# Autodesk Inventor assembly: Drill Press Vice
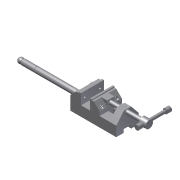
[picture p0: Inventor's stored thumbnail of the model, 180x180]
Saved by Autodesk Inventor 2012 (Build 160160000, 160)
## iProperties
Created: 2009-05
Part Number: Drill Press Vice
Document SubType Name: Assembly
Designer: Sham
Author: Sham
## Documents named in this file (9)
- C:\Users\CadCim\Documents\SAILESH\inventor-2011-fact-prt\c13-inv-2011-prt\c13_inv_2012_prt\Tutorials\c13_tut02_inv\Drill Press Vice.iam
- C:\Users\CadCim\Documents\SAILESH\inventor-2011-fact-prt\c13-inv-2011-prt\c13_inv_2012_prt\Tutorials\c13_tut02_inv\Base.ipt
- C:\Users\CadCim\Documents\SAILESH\inventor-2011-fact-prt\c13-inv-2011-prt\c13_inv_2012_prt\Tutorials\c13_tut02_inv\Safety Handle.ipt
- C:\Users\CadCim\Documents\SAILESH\inventor-2011-fact-prt\c13-inv-2011-prt\c13_inv_2012_prt\Tutorials\c13_tut02_inv\Jaw Face.ipt
- C:\Users\CadCim\Documents\SAILESH\inventor-2011-fact-prt\c13-inv-2011-prt\c13_inv_2012_prt\Tutorials\c13_tut02_inv\Movable Jaw.ipt
- C:\Users\CadCim\Documents\SAILESH\inventor-2011-fact-prt\c13-inv-2011-prt\c13_inv_2012_prt\Tutorials\c13_tut02_inv\Cap Screw.ipt
- C:\Users\CadCim\Documents\SAILESH\inventor-2011-fact-prt\c13-inv-2011-prt\c13_inv_2012_prt\Tutorials\c13_tut02_inv\Clamp Screw Handle.ipt
- C:\Users\CadCim\Documents\SAILESH\inventor-2011-fact-prt\c13-inv-2011-prt\c13_inv_2012_prt\Tutorials\c13_tut02_inv\Clamp Screw.ipt
- C:\Users\CadCim\Documents\SAILESH\inventor-2011-fact-prt\c13-inv-2011-prt\c13_inv_2012_prt\Tutorials\c13_tut02_inv\Handle Stop.ipt
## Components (13 placed, 8 different names)
1. Base:1 — Mate:2, Mate:3, Mate:7, Insert:10, Insert:11, Insert:12, Insert:13
2. Safety Handle:1
3. Jaw Face:1 — Insert:8, Insert:9, Mate:7
4. Jaw Face:2 — Insert:10, Insert:11
5. Movable Jaw:1 — Mate:2, Mate:3, Insert:2, Insert:3, Insert:4, Insert:8, Insert:9
6. Cap Screw:1 — Insert:2
7. Cap Screw:2 — Insert:3
8. Cap Screw:3 — Insert:13
9. Cap Screw:4 — Insert:12
10. Clamp Screw:1 — Insert:4, Mate:6, Rotation/Translation:2
11. Clamp Screw Handle:1 — Mate:6, Insert:5, Insert:6, Rotation/Translation:2
12. Handle Stop:1 — Insert:6, Mate:8
13. Handle Stop:2 — Insert:5
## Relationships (17: Insert 11, Mate 5, RelateRotateTranslate 1)
- Mate:2: Base:1 ↔ Movable Jaw:1
- Mate:3: Base:1 ↔ Movable Jaw:1
- Insert:2: Movable Jaw:1 ↔ Cap Screw:1
- Insert:3: Movable Jaw:1 ↔ Cap Screw:2
- Insert:4: Movable Jaw:1 ↔ Clamp Screw:1
- Mate:6: Clamp Screw:1 ↔ Clamp Screw Handle:1
- Insert:5: Clamp Screw Handle:1 ↔ Handle Stop:2
- Insert:6: Clamp Screw Handle:1 ↔ Handle Stop:1
- Insert:8: Jaw Face:1 ↔ Movable Jaw:1
- Insert:9: Jaw Face:1 ↔ Movable Jaw:1
- Mate:7: Base:1 ↔ Jaw Face:1
- Rotation/Translation:2 [RelateRotateTranslate]: Clamp Screw:1 ↔ Clamp Screw Handle:1
- Mate:8: Handle Stop:1
- Insert:10: Base:1 ↔ Jaw Face:2
- Insert:11: Base:1 ↔ Jaw Face:2
- Insert:12: Base:1 ↔ Cap Screw:4
- Insert:13: Base:1 ↔ Cap Screw:3
